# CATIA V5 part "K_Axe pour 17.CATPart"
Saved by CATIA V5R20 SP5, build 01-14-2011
Part number: Axe pour 17
Bounding box of the stored display mesh (mm): x 0 to 70, y -6 to 6, z -6 to 6
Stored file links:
  G:\Khaled_CFAO_2011\ST2M\ST2M_GR1\lpierredon\Khaled\CAD_thinkMOTION\K_Axe pour 17.CATPart
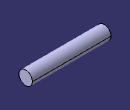
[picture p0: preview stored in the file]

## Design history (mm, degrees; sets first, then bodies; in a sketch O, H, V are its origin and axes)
Body1 (main body)
  Sketch1 on yz-plane, origin (0, 0, 0), H (0, 1, 0), V (0, 0, 1)
    circle A1 centre (0, 0) radius 6
    radius A1 = 6
  Pad1: profile Sketch1, direction (1, 0, 0), length 70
